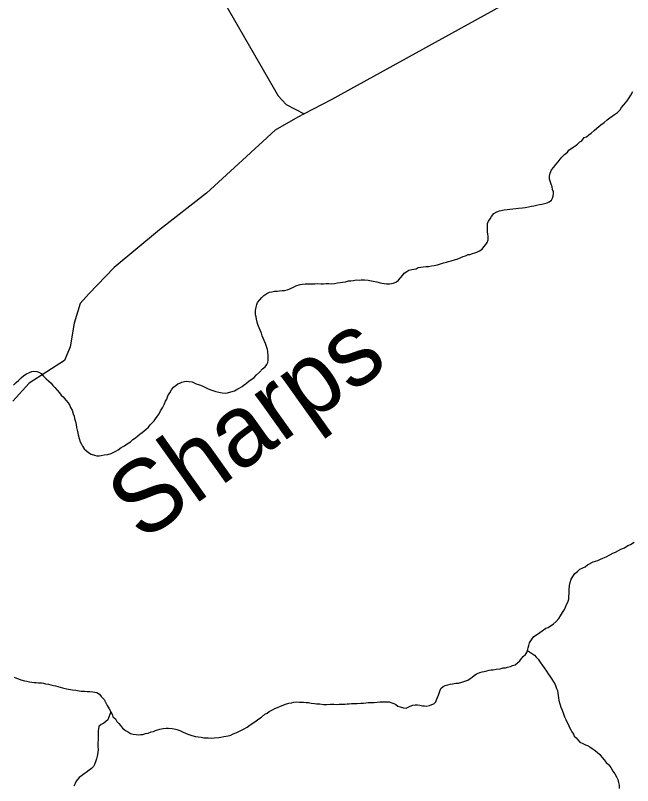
# Model space of a CAD drawing. Extents: x 1310247 to 1664935, y 284496 to 704931.
# Drawn here: x 1532360 to 1536646, y 484741 to 490091 of the extents above; entities that cross this region are included whole.
import ezdxf

# ---------------------------------------------------------------- set-up
doc = ezdxf.new("R2010")
doc.units = 0
for name, color, linetype in [('GM_X_County_Road_Text', 7, 'Continuous'), ('GM_X_County_Subdivision_Text', 7, 'Continuous'), ('GM_X_Minor_Lake_Text', 7, 'Continuous'), ('GM_X_Minor_River_Text', 7, 'Continuous')]:
    doc.layers.add(name, color=color, linetype=linetype)

msp = doc.modelspace()

# ---------------------------------------------------------------- linework, layer by layer
at = {"layer": 'GM_X_County_Road_Text'}
msp.add_lwpolyline([(1536564.9, 490615.9), (1534552.8, 489504.1), (1534365.4, 489406), (1534322, 489383.3), (1534163.9, 489293.5), (1533937.6, 489084.5), (1533687, 488855.7), (1533361.6, 488600.1), (1533046.2, 488340.3), (1532870.6, 488156.5), (1532809.3, 488089.2), (1532766.9, 487953.6), (1532740.3, 487789.5), (1532700.6, 487693.9), (1532455.1, 487535.2), (1532342.7, 487410.6)], dxfattribs=at)
at = {"layer": 'GM_X_County_Subdivision_Text'}
msp.add_lwpolyline([(1531611.1, 491488.5), (1531612.9, 491488.2), (1531855.7, 491449), (1532462.4, 491197), (1533005.3, 490980), (1533229.6, 490936.4), (1533344.9, 490862.4), (1533741.8, 490300.8), (1534185.7, 489531.8), (1534241, 489472.8), (1534365.4, 489406)], dxfattribs=at)
at = {"layer": 'GM_X_Minor_River_Text'}
for points in [[(1535794.2, 488745), (1535814.3, 488746.5), (1535836.5, 488750), (1535854.6, 488751.6), (1535882.8, 488754.9), (1535900.9, 488756.5), (1535923.1, 488760), (1535945.3, 488765.5), (1535959.5, 488767.1), (1535979.7, 488772.6), (1535999.9, 488776.2), (1536016, 488779.8), (1536034.2, 488783.4), (1536052.4, 488789), (1536066.7, 488796.6), (1536083, 488806.3), (1536089.3, 488820.2), (1536093.8, 488836.1), (1536096.1, 488850.1), (1536096.5, 488864.1), (1536090.9, 488882.3), (1536087.3, 488900.5), (1536079.8, 488918.7), (1536074.2, 488938.9), (1536068.6, 488953.1), (1536069.1, 488975.1), (1536073.6, 488995.1), (1536084.2, 489016.9), (1536098.8, 489036.6), (1536113.3, 489054.3), (1536129.8, 489074), (1536144.3, 489091.7), (1536154.7, 489105.5), (1536173.3, 489125.1), (1536193.8, 489140.7), (1536204.2, 489154.5), (1536218.5, 489166.1), (1536238.9, 489177.7), (1536263.5, 489195.2), (1536280, 489212.8), (1536294.2, 489218.5), (1536310.8, 489242.2), (1536325, 489247.8), (1536341.4, 489261.5), (1536357.8, 489273.1), (1536380.3, 489290.7), (1536396.9, 489308.3), (1536411.2, 489318), (1536425.5, 489329.7), (1536448, 489347.2), (1536470.6, 489364.7), (1536489, 489378.3), (1536505.4, 489390), (1536521.7, 489401.6), (1536542.2, 489417.2), (1536560.7, 489434.8), (1536569.2, 489450.6), (1536583.6, 489466.3), (1536598.2, 489486), (1536612.7, 489503.7), (1536623.1, 489517.5), (1536633.6, 489537.3), (1536648.3, 489561.1)], [(1534124.4, 488167.3), (1534140.6, 488171), (1534158.8, 488174.5), (1534176.9, 488176.1), (1534195, 488177.7), (1534213.1, 488179.2), (1534229.2, 488180.9), (1534247.4, 488184.4), (1534261.5, 488188.1), (1534275.8, 488195.8), (1534292.1, 488203.4), (1534308.3, 488211.1), (1534336.7, 488220.4), (1534354.9, 488224), (1534373, 488225.5), (1534391.1, 488227.1), (1534409.2, 488226.7), (1534425.2, 488226.3), (1534439.3, 488226), (1534457.4, 488227.5), (1534481.5, 488227), (1534499.6, 488226.5), (1534517.7, 488228.1), (1534535.7, 488227.6), (1534555.8, 488227.2), (1534575.9, 488228.7), (1534596.1, 488232.2), (1534616.3, 488235.7), (1534632.4, 488237.3), (1534652.6, 488240.9), (1534672.8, 488246.4), (1534688.9, 488248), (1534707, 488249.6), (1534727.2, 488253.1), (1534747.3, 488252.6), (1534761.4, 488254.3), (1534785.5, 488253.7), (1534809.5, 488251.1), (1534833.5, 488246.5), (1534855.5, 488242), (1534869.5, 488239.7), (1534885.5, 488235.3), (1534905.5, 488230.8), (1534921.5, 488228.4), (1534937.5, 488226), (1534957.6, 488225.5), (1534985.8, 488230.8), (1535006.1, 488240.4), (1535020.5, 488252.1), (1535034.9, 488267.8), (1535047.4, 488283.5), (1535059.9, 488301.3), (1535078.2, 488310.9), (1535092.5, 488320.5), (1535112.7, 488326.1), (1535126.8, 488327.8), (1535143, 488331.4), (1535157.3, 488339), (1535175.4, 488342.6), (1535191.5, 488344.2), (1535211.7, 488345.8), (1535229.8, 488347.3), (1535250, 488350.9), (1535268.1, 488354.4), (1535290.3, 488357.9), (1535312.6, 488365.4), (1535332.8, 488370.9), (1535353.1, 488376.5), (1535367.2, 488380.1), (1535387.4, 488385.7), (1535409.7, 488393.2), (1535432, 488400.6), (1535454.3, 488410.1), (1535468.5, 488415.8), (1535484.8, 488421.4), (1535505, 488429), (1535519.1, 488430.6), (1535535.3, 488436.3), (1535549.5, 488441.9), (1535563.7, 488445.6), (1535584, 488455.2), (1535600.4, 488466.8), (1535612.8, 488482.5), (1535627.3, 488500.3), (1535635.7, 488514.1), (1535642.2, 488532), (1535642.8, 488556.1), (1535641.1, 488570.1), (1535639.6, 488588.2), (1535638.1, 488610.3), (1535638.6, 488628.4), (1535639, 488644.4), (1535645.4, 488660.3), (1535657.9, 488678.1), (1535666.3, 488693.9), (1535682.9, 488713.6), (1535703.3, 488725.1), (1535721.5, 488732.7), (1535753.9, 488740), (1535776.1, 488743.5), (1535794.2, 488745)], [(1532941, 487032.2), (1532955.1, 487033.9), (1532977.3, 487037.3), (1533001.5, 487040.8), (1533023.8, 487048.3), (1533044, 487055.8), (1533058.3, 487063.5), (1533072.6, 487073.2), (1533095.1, 487088.7), (1533117.5, 487100.2), (1533135.9, 487115.8), (1533158.4, 487129.3), (1533174.8, 487144.9), (1533193.2, 487156.5), (1533209.6, 487170.2), (1533224, 487181.9), (1533240.3, 487193.5), (1533254.7, 487205.2), (1533269, 487216.9), (1533283.4, 487230.6), (1533295.9, 487246.3), (1533310.3, 487260), (1533322.7, 487273.8), (1533333.1, 487289.6), (1533343.6, 487305.4), (1533358.1, 487323.1), (1533368.6, 487342.9), (1533381.2, 487364.7), (1533395.9, 487392.4), (1533402.4, 487410.3), (1533410.8, 487424.1), (1533419.4, 487448), (1533432, 487469.8), (1533444.6, 487489.5), (1533457.1, 487507.3), (1533473.4, 487518.9), (1533487.8, 487532.6), (1533502, 487536.3), (1533516.2, 487542), (1533534.4, 487547.6), (1533548.5, 487549.2), (1533566.6, 487548.8), (1533588.6, 487544.3), (1533602.5, 487537.9), (1533616.4, 487531.5), (1533632.3, 487527.1), (1533646.3, 487522.8), (1533662.1, 487514.4), (1533680, 487505.9), (1533697.9, 487497.5), (1533717.8, 487489), (1533737.7, 487482.5), (1533751.6, 487478.1), (1533771.6, 487473.6), (1533795.6, 487469), (1533815.6, 487466.5), (1533833.8, 487468.1), (1533856, 487475.6), (1533882.3, 487483), (1533904.8, 487496.5), (1533919, 487504.2), (1533935.4, 487513.8), (1533949.6, 487523.5), (1533964, 487535.2), (1533984.5, 487552.8), (1534002.9, 487564.4), (1534017.3, 487576), (1534033.8, 487593.7), (1534054.3, 487613.3), (1534075, 487634.8), (1534093.4, 487648.5), (1534105.9, 487666.2), (1534112.3, 487680.1), (1534114.6, 487694.1), (1534115, 487710.1), (1534115.4, 487724.2), (1534112.2, 487756.3), (1534110.5, 487770.4), (1534106.8, 487784.6), (1534097.4, 487810.9), (1534088, 487833.2), (1534080.3, 487849.4), (1534074.7, 487865.6), (1534069.1, 487883.8), (1534059.6, 487904.1), (1534052, 487920.3), (1534044.5, 487944.6), (1534038.9, 487960.8), (1534033.4, 487981), (1534031.8, 487997), (1534028.1, 488011.2), (1534026.5, 488027.3), (1534026.9, 488041.3), (1534031.4, 488063.3), (1534035.9, 488083.2), (1534042.3, 488097.1), (1534056.8, 488114.8), (1534071.3, 488130.5), (1534085.7, 488144.2), (1534106.2, 488159.8), (1534124.4, 488167.3)], [(1532346.5, 487522), (1532365, 487539.7), (1532383.6, 487557.3), (1532400, 487572.9), (1532418.5, 487590.5), (1532436.9, 487600.1), (1532457.2, 487609.7), (1532473.5, 487617.3), (1532487.6, 487619), (1532509.6, 487616.4), (1532523.5, 487612.1), (1532539.4, 487603.7), (1532555, 487585.2), (1532572.6, 487566.8), (1532590.4, 487552.3), (1532608, 487535.8), (1532619.7, 487519.5), (1532633.4, 487507.1), (1532651, 487488.6), (1532666.6, 487468.2), (1532678.3, 487453.9), (1532692.1, 487441.5), (1532709.5, 487417), (1532727.2, 487400.5), (1532738.8, 487382.2), (1532742.4, 487368), (1532754, 487347.7), (1532761.4, 487323.4), (1532769.1, 487307.2), (1532770.7, 487291.1), (1532776.1, 487268.9), (1532781.7, 487248.7), (1532785.2, 487228.6), (1532790.5, 487200.3), (1532796, 487178.1), (1532803.4, 487151.9), (1532810.8, 487127.6), (1532818.5, 487113.4), (1532826.1, 487099.2), (1532837.7, 487080.8), (1532853.4, 487066.4), (1532867.2, 487054), (1532887, 487043.5), (1532908.9, 487035), (1532924.9, 487032.6), (1532941, 487032.2)], [(1536181.2, 485980.9), (1536187.7, 485998.8), (1536196.1, 486014.7), (1536202.7, 486036.6), (1536203.1, 486052.6), (1536205.7, 486078.7), (1536206.3, 486100.7), (1536209, 486130.8), (1536211.6, 486152.8), (1536220.2, 486174.6), (1536234.9, 486200.3), (1536245.3, 486214.1), (1536263.7, 486227.7), (1536280.1, 486243.4), (1536300.5, 486252.9), (1536316.7, 486260.6), (1536333.1, 486274.2), (1536371.8, 486295.4), (1536404.2, 486304.6), (1536422.5, 486314.2), (1536440.7, 486319.8), (1536463.1, 486329.3), (1536487.5, 486342.7), (1536507.9, 486354.3), (1536528.2, 486361.8), (1536548.6, 486373.4), (1536564.9, 486383), (1536589.2, 486392.4), (1536613.7, 486407.9), (1536632, 486415.5), (1536656.5, 486431)], [(1534609.5, 485306.6), (1534625.6, 485306.2), (1534647.7, 485307.7), (1534663.8, 485309.3), (1534677.9, 485308.9), (1534694, 485310.6), (1534716.1, 485312), (1534734.2, 485311.6), (1534758.4, 485313), (1534778.5, 485314.5), (1534792.6, 485316.2), (1534808.7, 485317.8), (1534822.7, 485317.5), (1534836.8, 485319.1), (1534850.9, 485318.8), (1534873, 485320.3), (1534891.2, 485321.9), (1534907.3, 485323.5), (1534927.3, 485323), (1534941.4, 485322.6), (1534955.5, 485322.3), (1534973.4, 485315.9), (1534987.3, 485311.5), (1535001.2, 485305.2), (1535017, 485292.7), (1535033, 485288.3), (1535054.9, 485281.8), (1535072.9, 485279.3), (1535087.1, 485285), (1535101.4, 485292.7), (1535119.6, 485300.3), (1535135.7, 485301.9), (1535151.8, 485301.5), (1535169.8, 485299.1), (1535187.8, 485294.6), (1535201.8, 485294.3), (1535215.8, 485292), (1535236.1, 485297.5), (1535252.3, 485305.1), (1535266.5, 485308.8), (1535278.9, 485322.5), (1535285.3, 485336.4), (1535291.7, 485352.3), (1535298.1, 485368.2), (1535302.5, 485382.1), (1535306.8, 485396.1), (1535315.4, 485416), (1535329.8, 485429.6), (1535344, 485435.3), (1535362.2, 485440.9), (1535380.4, 485444.5), (1535396.5, 485448.1), (1535418.7, 485451.6), (1535436.8, 485453.1), (1535461.1, 485458.6), (1535481.3, 485466.1), (1535501.6, 485473.7), (1535518, 485485.3), (1535532.3, 485495), (1535546.6, 485506.7), (1535562.9, 485516.3), (1535585.3, 485525.8), (1535601.5, 485531.4), (1535615.6, 485533.1), (1535633.8, 485538.7), (1535650, 485542.3), (1535664.1, 485544), (1535678.2, 485545.6), (1535698.4, 485549.2), (1535726.6, 485552.5), (1535746.8, 485558), (1535762.9, 485559.7), (1535777.1, 485563.3), (1535797.3, 485568.9), (1535811.5, 485574.5), (1535829.7, 485580.1), (1535846.1, 485593.8), (1535862.5, 485607.4), (1535875, 485623.2), (1535887.4, 485636.9), (1535901.8, 485650.6), (1535912.2, 485664.4), (1535916.6, 485680.3), (1535921, 485698.3), (1535925.4, 485714.2), (1535929.9, 485732.2), (1535944.5, 485753.9), (1535961.1, 485775.6), (1535979.5, 485787.2), (1536002, 485804.7), (1536018.4, 485816.3), (1536042.9, 485833.8), (1536059.1, 485839.4), (1536075.5, 485851.1), (1536093.9, 485862.7), (1536114.4, 485880.2), (1536133, 485901.8), (1536145.5, 485919.6), (1536160.2, 485943.3), (1536172.7, 485963.1), (1536181.2, 485980.9)], [(1535916.6, 485680.3), (1535964, 485647.1), (1535975.7, 485632.8), (1535991.4, 485618.3), (1536004.9, 485598), (1536020.4, 485575.5), (1536032.1, 485559.2), (1536047.6, 485536.7), (1536059.1, 485516.4), (1536070.8, 485500.1), (1536086.3, 485479.6), (1536097.9, 485461.3), (1536109.5, 485443), (1536118.9, 485414.6), (1536124.5, 485400.5), (1536126.1, 485382.4), (1536129.7, 485366.2), (1536131.3, 485350.1), (1536134.9, 485332), (1536140.4, 485309.8), (1536147.8, 485285.5), (1536157.3, 485265.2), (1536166.7, 485238.9), (1536174.3, 485218.7), (1536181.8, 485200.4), (1536191.4, 485180.1), (1536201, 485163.8), (1536204.7, 485149.7), (1536218.2, 485129.3), (1536223.9, 485115.1), (1536235.6, 485098.8), (1536241.2, 485084.6), (1536255, 485072.3), (1536266.7, 485057.9), (1536280.4, 485043.6), (1536300.2, 485033), (1536320.1, 485024.5), (1536334, 485020.2), (1536349.9, 485009.8), (1536365.7, 484999.4), (1536379.5, 484989), (1536399.1, 484972.5), (1536418.8, 484956), (1536432.4, 484937.6), (1536448, 484919.1), (1536463.7, 484900.7), (1536481.3, 484884.2), (1536494.9, 484865.8), (1536508.4, 484841.4), (1536522, 484823), (1536535.6, 484802.6), (1536543.1, 484784.4), (1536548.6, 484762.2), (1536552.2, 484744.1), (1536553.6, 484720)], [(1532352.2, 485493.5), (1532368.1, 485487), (1532382.1, 485482.7), (1532398, 485476.3), (1532423.9, 485469.6), (1532439.9, 485465.2), (1532457.9, 485460.8), (1532473.9, 485458.4), (1532489.9, 485458), (1532504, 485457.7), (1532520, 485455.3), (1532540.1, 485454.8), (1532554.1, 485452.5), (1532568, 485448.1), (1532590.1, 485445.6), (1532606, 485441.2), (1532624, 485436.7), (1532638, 485434.4), (1532654, 485430), (1532671.9, 485423.5), (1532687.8, 485419.1), (1532705.8, 485414.7), (1532727.8, 485410.1)], [(1532727.8, 485410.1), (1532741.8, 485407.8), (1532755.8, 485405.5), (1532779.8, 485402.9), (1532801.9, 485400.3), (1532815.9, 485398), (1532840, 485397.4), (1532858, 485395), (1532876.1, 485394.5), (1532898.1, 485392), (1532912.1, 485389.7), (1532926.1, 485387.3), (1532943.9, 485376.8), (1532955.6, 485360.5), (1532977.1, 485337.9), (1532988.6, 485315.6), (1532998.2, 485297.3), (1533011.7, 485274.9), (1533023.2, 485252.5), (1533034.7, 485232.2), (1533036.4, 485218.1), (1533054.1, 485203.6), (1533063.7, 485185.4), (1533077.5, 485173), (1533089.2, 485158.7), (1533104.8, 485140.2), (1533124.4, 485123.7), (1533144.3, 485113.2), (1533160.1, 485102.8), (1533178, 485098.3), (1533198.1, 485095.8), (1533214.1, 485093.4), (1533230.2, 485095.1), (1533244.3, 485096.7), (1533262.5, 485102.3), (1533282.7, 485105.8), (1533303, 485113.4), (1533319.1, 485117), (1533333.4, 485124.7), (1533347.5, 485128.3), (1533361.8, 485134), (1533385.9, 485137.5), (1533406.1, 485139), (1533424.2, 485140.5), (1533448.2, 485138), (1533462.2, 485135.6), (1533480.2, 485131.2), (1533502.1, 485122.6), (1533520, 485114.2), (1533545.8, 485103.5), (1533563.7, 485095), (1533585.6, 485088.5), (1533611.6, 485081.9), (1533629.6, 485079.4), (1533649.6, 485076.9), (1533667.6, 485072.5), (1533681.6, 485072.1), (1533697.7, 485071.8), (1533719.8, 485071.2), (1533739.9, 485072.7), (1533772.1, 485076), (1533786.2, 485077.6), (1533806.4, 485081.2), (1533836.7, 485086.5), (1533854.9, 485092), (1533871.1, 485099.7), (1533897.5, 485109.1), (1533921.9, 485120.5), (1533944.3, 485134), (1533968.8, 485147.5), (1533991.2, 485163), (1534021.9, 485184.3), (1534050.6, 485205.7), (1534068.9, 485215.3), (1534091.5, 485236.8), (1534107.8, 485244.4), (1534122.1, 485256.1), (1534144.5, 485267.6), (1534160.8, 485277.3), (1534181.1, 485282.8), (1534201.4, 485292.3), (1534219.7, 485299.9), (1534235.9, 485305.6), (1534258.1, 485313), (1534278.3, 485316.6), (1534292.5, 485320.2), (1534310.6, 485321.8), (1534332.7, 485321.3), (1534360.8, 485320.6), (1534378.8, 485318.2), (1534394.9, 485317.8), (1534414.8, 485313.3), (1534436.9, 485310.7), (1534450.9, 485308.4), (1534473, 485307.9), (1534499, 485305.2), (1534523.1, 485304.6), (1534547.2, 485306.1), (1534571.3, 485305.5), (1534595.4, 485304.9), (1534609.5, 485306.6)], [(1533023.2, 485252.5), (1533001.8, 485198.9), (1532987.4, 485187.2), (1532973.1, 485175.5), (1532954.7, 485165.9), (1532940.3, 485152.2), (1532935.9, 485136.3), (1532935.6, 485122.2), (1532935.2, 485108.2), (1532934.8, 485092.2), (1532934.4, 485074.1), (1532934, 485060.1), (1532933.5, 485038), (1532932.9, 485016), (1532934.3, 484991.8), (1532931.8, 484969.8), (1532927.2, 484945.9), (1532922.7, 484927.9), (1532916.1, 484906), (1532909.7, 484888.1), (1532903.3, 484874.2), (1532888.9, 484860.5), (1532872.5, 484848.9), (1532852, 484831.3), (1532837.7, 484823.6), (1532819.3, 484808), (1532802.9, 484796.4), (1532782.2, 484772.8), (1532775.8, 484754.9), (1532765.3, 484737.1)]]:
    msp.add_lwpolyline(points, dxfattribs=at)

# ---------------------------------------------------------------- texts
at = {"layer": 'GM_X_Minor_Lake_Text'}
msp.add_text('Sharps', height=499.98, rotation=35.4561, dxfattribs=at).set_placement((1533237.7, 486428.4))

doc.saveas('drawing.dxf')
